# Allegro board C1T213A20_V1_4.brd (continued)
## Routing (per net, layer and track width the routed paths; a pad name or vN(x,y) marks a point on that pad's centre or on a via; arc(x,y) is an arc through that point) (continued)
N19937731: length 2.3
  TOP w0.4: R18.2 21.63,28.44 21.19,28.88 J57.2
N19956971: length 1.2
  TOP w0.2: U1.63 L5.1
N19973210: length 3.3
  TOP w0.35: L1.2 C7.2 J1.1
N19973218: length 1.3
  TOP w0.35: L5.2 C6.2 L1.1
N198520641: length 1.3
  TOP w0.2: D4.A R20.2
N198520720: length 1.3
  TOP w0.2: D1.A R22.2
N198520801: length 1.3
  TOP w0.2: D2.A R21.2
N198520880: length 1.3
  TOP w0.2: D3.A R23.2

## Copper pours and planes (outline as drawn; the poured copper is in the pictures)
VBUS on POWER: 5.9,46.83 4.25,48.48 4.25,52.73 0.3,52.73 0.3,65.53 1.11,67.47 3.05,68.28 74.55,68.28 76.49,67.47 77.3,65.53 77.3,54.53 69.35,54.53 69.35,62.58 66.9,65.03 40.45,65.03 40.45,66.93 21.05,66.93 21.05,65.88 22.25,64.68 22.25,64.13 10.8,64.13 9.55,62.88 9.55,51.08 10.25,50.38 10.25,49.18 7.9,46.83
VDD_L on POWER: 23,64.73 22.7,65.03 22.6,65.03 21.55,66.08 21.55,66.43 39.95,66.43 39.95,65.03 39,65.03 38.3,65.73 24,65.73
0 on TOP: 34.35,59.03 34.71,59.03 35.27,59.59 36.72,59.59 36.72,61.49 33.63,61.49 33.63,63.94 34.19,63.94 34.64,64.39 34.64,68.28 74.55,68.28 76.5,67.48 77.3,65.53 77.3,4.19 75.95,2.84 45.26,2.84 42.72,0.3 10.2,0.3 7.66,2.84 1,2.84 0.51,3.05 0.3,3.54 0.3,65.53 1.1,67.48 3.05,68.28 31.55,68.28 31.55,64.37 31.98,63.94 32.57,63.94 32.57,60.58 33.58,60.58 33.58,59.59 34.55,59.59 34.35,59.39 ; 51 cut-outs
0 on BOTTOM: 10.2,0.3 7.66,2.84 1,2.84 0.51,3.05 0.3,3.54 0.3,65.53 1.1,67.48 3.05,68.28 74.55,68.28 76.5,67.48 77.3,65.53 77.3,4.19 75.95,2.84 45.26,2.84 42.72,0.3 ; 14 cut-outs
0 on GND: 10.2,0.3 7.66,2.84 1,2.84 0.51,3.05 0.3,3.54 0.3,65.53 1.1,67.48 3.05,68.28 74.55,68.28 76.5,67.48 77.3,65.53 77.3,4.19 75.95,2.84 45.26,2.84 42.72,0.3
TL_AVD on POWER: 32.2,29.93 23.45,38.68 23.45,43.48 28.4,48.43 29.4,48.43 31.2,46.63 32.5,46.63 33,47.13 34.65,47.13 34.65,42.48 41.3,35.83 53.2,35.83 53.35,35.68 53.35,35.13 51.65,35.13 51.65,29.93
TL_AVDD1V4 on POWER: 4.8,17.03 2.35,19.48 2.35,40.68 2.9,41.23 5.9,41.23 6.05,41.08 6.05,40.13 4.3,40.13 3.15,38.98 3.15,32.38 13.8,21.73 41.35,21.73 41.35,23.73 57.4,23.73 60.25,26.58 60.25,36.58 56,40.83 53.2,40.83 51.75,42.28 51.75,43.08 42.9,51.93 40.8,51.93 40.1,51.23 37.45,51.23 37.45,52.83 42.9,52.83 50.4,45.33 53.1,45.33 57.15,41.28 57.15,40.58 59.7,38.03 60.9,38.03 62.05,36.88 62.05,17.03
TL_AVDD3 on POWER: 10.2,0.3 7.66,2.84 1,2.84 0.51,3.05 0.3,3.54 0.3,30.33 1.85,30.33 1.85,19.28 4.6,16.53 62.3,16.53 62.55,16.78 62.55,37.08 61.35,38.28 62.85,39.78 62.85,50.98 54.8,59.03 44.6,59.03 40.6,55.03 37.45,55.03 37.45,65.23 38.1,65.23 38.8,64.53 66.7,64.53 68.85,62.38 68.85,54.03 77.3,54.03 77.3,4.19 75.95,2.84 45.26,2.84 42.72,0.3
TL_DVDD1V4 on POWER: 17.4,24.23 6.7,34.93 5.3,34.93 5.05,35.18 5.05,36.58 5.2,36.73 10.2,36.73 19.2,27.73 58.15,27.73 58.15,37.08 55.7,39.53 50.3,39.53 49.15,40.68 49.15,43.98 42.3,50.83 41.6,50.83 41,50.23 37.45,50.23 37.45,50.73 40.3,50.73 41,51.43 42.7,51.43 51.25,42.88 51.25,42.08 53,40.33 55.8,40.33 59.75,36.38 59.75,26.78 57.2,24.23 ; 1 cut-out
TL_FVDD1V8 on POWER: 59.9,38.53 57.65,40.78 57.65,41.48 53.3,45.83 50.6,45.83 43.1,53.33 37.45,53.33 37.45,54.53 40.8,54.53 41.55,55.28 42.4,54.43 45.3,54.43 52.4,47.33 56.7,47.33 57.55,46.48 57.55,42.58 58.3,41.83 62.35,41.83 62.35,39.98 60.9,38.53
TL_RFVDD1V4 on POWER: 0.3,42.83 0.3,52.23 3.75,52.23 3.75,48.28 5.7,46.33 8.1,46.33 10.75,48.98 10.75,50.23 11.1,50.23 23.4,62.53 30,62.53 35.45,57.08 35.45,56.43 31.4,56.43 30.3,57.53 21.5,57.53 9.5,45.53 4.6,45.53 2.5,47.63 1.6,47.63 1.05,47.08 1.05,45.98 3.4,43.63 9.35,43.63 9.35,42.83
TL_VBAT on POWER: 52.15,29.93 52.15,34.63 53.85,34.63 53.85,35.88 53.4,36.33 41.5,36.33 35.15,42.68 35.15,47.28 35.95,48.08 35.95,57.28 30.2,63.03 23.2,63.03 10.9,50.73 10.6,50.73 10.05,51.28 10.05,62.68 11,63.63 22.6,63.63 24.2,65.23 36.95,65.23 36.95,45.18 45.3,36.83 54.4,36.83 54.95,36.28 54.95,35.08 53.25,33.38 53.25,32.28 55.35,30.18 55.35,29.93
TL_VBUS on POWER: 9.85,42.83 9.85,44.13 3.6,44.13 1.55,46.18 1.55,46.88 1.8,47.13 2.3,47.13 4.4,45.03 9.7,45.03 21.7,57.03 30.1,57.03 31.2,55.93 35.45,55.93 35.45,48.28 34.8,47.63 33.95,47.63 33.95,52.98 33,53.93 22.6,53.93 11.5,42.83
TL_VDD1V4_O on POWER: 19.4,28.23 10.4,37.23 5.35,37.23 5.35,38.28 5.4,38.33 23.1,38.33 32,29.43 57.05,29.43 57.05,36.58 55.2,38.43 49.2,38.43 44.95,42.68 44.95,43.38 39,49.33 37.45,49.33 37.45,49.73 41.2,49.73 41.8,50.33 42.1,50.33 48.65,43.78 48.65,40.48 50.1,39.03 55.5,39.03 57.65,36.88 57.65,28.23
TL_VDD1V8_O on POWER: 58.5,42.33 58.05,42.78 58.05,46.68 56.9,47.83 52.6,47.83 45.5,54.93 42.6,54.93 41.9,55.63 44.8,58.53 54.6,58.53 62.35,50.78 62.35,42.33
TL_VDD3_DCDC on POWER: 55.85,29.93 55.85,30.38 53.75,32.48 53.75,33.18 55.45,34.88 55.45,36.48 54.6,37.33 45.5,37.33 37.45,45.38 37.45,48.83 38.8,48.83 44.45,43.18 44.45,42.48 49,37.93 55,37.93 56.55,36.38 56.55,29.93
TL_VDDCORE on POWER: 14,22.23 3.65,32.58 3.65,38.78 4.5,39.63 13.4,39.63 21.8,48.03 25.8,48.03 27.4,49.63 30.8,49.63 32.65,47.78 32.65,47.48 32.3,47.13 31.4,47.13 29.6,48.93 28.2,48.93 22.95,43.68 22.95,38.83 5.2,38.83 4.85,38.48 4.85,37.08 4.55,36.78 4.55,34.98 5.1,34.43 6.5,34.43 17.2,23.73 40.85,23.73 40.85,22.23
TL_VDDDEC on POWER: 0.3,30.83 0.3,42.33 11.7,42.33 22.8,53.43 32.8,53.43 33.45,52.78 33.45,47.63 33.15,47.63 33.15,47.98 31,50.13 27.2,50.13 25.6,48.53 21.6,48.53 13.2,40.13 6.55,40.13 6.55,41.28 6.1,41.73 2.7,41.73 1.85,40.88 1.85,30.83

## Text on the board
Ref Des/Silkscreen Bottom: TDO | GND | REF | BEVK | VDDDEC | VBUS | 1V4 | TDI | SWS | TCK | TMS | NC | USBVBUS | RFVDD1V4 | AVDD1V4 | VDD1V4_O | DVDD1V4 | VDDCORE | VDD1V8_O | FVDD1V8 | VFLASH | AVD | VDD3_DCDC | VBAT | VCOM | VDD_L | VIO | VDW | 1V8C | AVDD3 | VBATADJ | VUP
User.Comments: RESET | IOREF | 3V3 | 5V | TX | RX | # | SCL | AREF | GND | 13 | 12 | 11 | 10 | 9 | 8 | 7 | 6 | 5 | 4 | 3 | 2 | 1 | 0 | SDA | A0 | A5 | VIN | A2 | A1 | A4 | A3 | [#=PWM] | www.arduino.cc | UNO_Rev3.01 | #4 | #3 | #1 | #2 | TOP | #5 | BOTTOM | POWER | ANALOG IN | L | ON | DIGITAL | R10 | R9 | ESD1 | D1 | X1 | E1 | E2 | C3 | C4 | C5 | Cp1 | U2 | ZU4 | C12 | C2 | U1 | R2 | R1 | R3 | R8 | U5' | U5 | C8 | C10 | D2 | F1 | C1 | T1 | R6 | U3 | R14 | R15 | ICSP | R13 | Y2 | R12 | R7 | C11 | C9 | R4 | RESET-EN | R11 | C6 | L1 | X2 | C7 | Y1 | IOL | IOH | GROUND | Xduino
Ref Des/Silkscreen Top: APLM | ANLM | APLL | ANLL | MAL | DM | DP | PE1 | PE2 | PA0 | PA4 | PA3 | PB0 | PB2 | PB4 | PB5 | PB6 | PB7 | PA5 | PA6 | PE0 | PE3 | PA2 | PA1 | PB1 | PB3 | NC | LED_B | LED_G | LED_W | LED_R | APL | ANL | P20 | VDD25EF | VREFP_CODEC | K1 | K3 | K2 | K4 | PD3 | PD2 | DCK2 | DCK1 | DDAT | PC7 | PC5 | PC2 | PC0 | PC3 | PC1 | P29 | P26 | APR | ANR | CHIP_RESET | APRL | ANRL | CRST | PD7 | PD6 | PD5 | PD4 | PC6 | PC4 | KEY1 | KEY2 | KEY3 | KEY4 | P28 | P25 | APRM | ANRM | FLASH_RESET | TLSR9518ADK80D | C1T213A20_V1.4 | 2022-03-06 | SPK-L | SPK-R | A-MIC-L | A-MIC-R
COMPVAL_TYPE_BOTTOM: FIGURE | SIZE | 0.3 | 0.5 | 0.7 | 0.9 | 1.0 | DRILL CHART: TOP to BOTTOM | ALL UNITS ARE IN MILLIMETERS | PLATED | NON-PLATED | QTY | 492 | 2 | 4 | 18 | 8
